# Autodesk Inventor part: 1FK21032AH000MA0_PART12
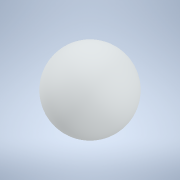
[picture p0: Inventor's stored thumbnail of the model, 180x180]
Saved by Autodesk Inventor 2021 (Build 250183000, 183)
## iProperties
Created: 2025-04
Part Number: 1FK21032AH000MA0_PART12
Material: Generic
Catalog Web Link: www.3dfindit.com
Description: -Servo synchronous motor
Document SubType Name: Modeling
Designer: psAdmin
Mass: 0.113097 g
Surface Area: 1.13097 cm^2
Volume: 0.113097 cm^3
Density: 1 g/cm^3
Appearance: PSOLRGB-212-217-219
Category: PARTsolutions
Title: 1FK21032AH000MA0_PART12
Author: Cadenas PARTsolutions
Comments: Servo synchronous motor
Sending System: PARTsolutions
Preprocessor: ST-DEVELOPER v19.3
PSOL_IDENT_0: {$CADENAS_DATA/23d-libs/siemens_ag/_cat_/45/10/1fk21032ah000ma0.prj},216 {VTYP=3D},{NB=1FK21032AH000
PSOL_IDENT_1: MA0_PART12},{LINA=1FK21032AH000MA0_PART12},{NN=1FK21032AH000MA0_PART12},{NOPRJ=TRUE},{DATE=19.08.202
PSOL_IDENT_2: 5 14:00:35},{GEOMDATE=30.07.2025 02:02:03},{VERSION=},{LINEID=10},{WBVAR=},{WBNUMERIC=}  {NB=1FK2103
PSOL_IDENT_3: 2AH000MA0_PART12},{LINA=1FK21032AH000MA0_PART12},{KT=DUMMY},{PREVIEW=../../../_pool_/14/8e/p_d211_xx
PSOL_IDENT_4: _00426j.png},{DESCSHORT=SIMOTICS S-1FK2 HD, SINAMICS S210 3AC 400V-480V, 0.59 Nm, 4500 rpm},{DESCLON
PSOL_IDENT_5: G=SIMOTICS S-1FK2 HD servo motor M0=0.64 Nm; PN = 0.28 kW at nN=4500 rpm (380-480 V); PN = 0.167 kW
PSOL_IDENT_6: at nN=2500 rpm (200-240 V); degree of protection IP64; cylindrical shaft D14 x 30 mm; absolute encod
PSOL_IDENT_7: er 22-bit + 12-bit multiturn (encoder AM22DQC); with OCC interface; plug size M17, rotatable; SIMOTI
PSOL_IDENT_8: CS S-1FK2 servomotorfor a wide range of uses in industrial environments. SIMOTICS S‑1FK2 servomotors
PSOL_IDENT_9: are compact synchronous motors with a high dynamic performance that set themselves apart as a resul
PSOL_IDENT_10: t of their high power density, degree of protection and overload capability. The motors are availabl
PSOL_IDENT_11: e in two variants: as High Dynamic variant (highest dynamic performance as a result of the low intri
PSOL_IDENT_12: nsic moment of inertia for applications demanding a high dynamic performance with low moved masses)
PSOL_IDENT_13: - and as Compact variant (precise and stable closed-loop control for medium up to large moved masses
PSOL_IDENT_14: as a result of a medium intrinsic moment of inertia). SIMOTICSS‑1FK2 servomotors fully exploit thei
PSOL_IDENT_15: r strengths in a system with the SINAMICSS210 frequency converter and simple connection using the on
PSOL_IDENT_16: e cable connection (OCC). Advantages include the short control and positioning times, fast and preci
PSOL_IDENT_17: se correction of disturbing quantities as well as stable control with a high dynamic performance. Th
PSOL_IDENT_18: e servo motors can be configured to address a wide range of requirements. For example with and witho
PSOL_IDENT_19: ut holding brake, IP64 or IP65 degree of protection, singleturn or multiturn absolute encoders - to
PSOL_IDENT_20: name just a few. Further, the servomotors are available in different shaft heights extending from 20
PSOL_IDENT_21: to 100. A shaft sealing ring is available to achieve an IP65 degree of protection and for subsequen
PSOL_IDENT_22: t mounting at the motor or as spare part. SIMOTICS - the optimum motor for each and every motion con
PSOL_IDENT_23: trol application.},{INTNO=195125335004},{SUPPLIERALTNO=1FK2103-2AH00-0MA0},{MANUID=1FK21032AH000MA0}
PSOL_IDENT_24: ,{MANUNAME=Siemens},{MANUTYPEDESC=SYNCHRONOUS MOTOR 1FK2 HD 0,64 NM},{AAU732=SIMOTICS},{AAO057=S-1FK
PSOL_IDENT_25: 2},{AAU734=SIMOTICS S-1FK2 HD servo motor M0=0.64 Nm; PN = 0.28 kW at nN=4500 rpm (380-480 V); PN =
PSOL_IDENT_26: 0.167 kW at nN=2500 rpm (200-240 V); degree of protection IP64; cylindrical shaft D14 x 30 mm; absol
PSOL_IDENT_27: ute encoder 22-bit + 12-bit multiturn (encoder AM22DQC); with OCC interface; plug size M17, rotatabl
PSOL_IDENT_28: e;},{AAW338=SYNCHRONOUS MOTOR 1FK2 HD 0,64 NM},{AAO742=SIMOTICS},{AAO663=4034106444624},{NOCUPEROU=1
PSOL_IDENT_29: },{PRICEQUANTITY=1},{QUANTITYMIN=1},{QUANTITYINT=1},{CTN=85015100},{COO=RO},{AAO676=1FK2103-2AH00-0M
PSOL_IDENT_30: A0},{AAO677=Siemens AG},{ORDERUNIT=C62},{CONTENTUNIT=C62}
NB: 1FK21032AH000MA0_PART12
NT: Servo synchronous motor
NBSYN: $MANUID._PART12
LINA: 1FK21032AH000MA0_PART12
CATALOG: SIEMENS
PREVIEW: ../../../_pool_/14/8e/p_d211_xx_00426j.png
DESCSHORT: SIMOTICS S-1FK2 HD, SINAMICS S210 3AC 400V-480V, 0.59 Nm, 4500 rpm
DESCLONG: SIMOTICS S-1FK2 HD servo motor M0=0.64 Nm; PN = 0.28 kW at nN=4500 rpm (380-480 V); PN = 0.167 kW at nN=2500 rpm (200-240 V); degree of protection IP64; cylindr
INTNO: 195125335004
SUPPLIERALTNO: 1FK2103-2AH00-0MA0
MANUID: 1FK21032AH000MA0
MANUNAME: Siemens
MANUTYPEDESC: SYNCHRONOUS MOTOR 1FK2 HD 0,64 NM
AAU732: SIMOTICS
AAO057: S-1FK2
AAU734: SIMOTICS S-1FK2 HD servo motor M0=0.64 Nm; PN = 0.28 kW at nN=4500 rpm (380-480 V); PN = 0.167 kW at nN=2500 rpm (200-240 V); degree of protection IP64; cylindr
AAW338: SYNCHRONOUS MOTOR 1FK2 HD 0,64 NM
AAO742: SIMOTICS
AAO663: 4034106444624.0
NOCUPEROU: 1
PRICEQUANTITY: 1
QUANTITYMIN: 1
QUANTITYINT: 1
CTN: 85015100
COO: RO
ARTICLENO: 1FK21032AH000MA0_PART12
BOMINFO: 1FK21032AH000MA0_PART12
CREATOR: CADENAS GmbH
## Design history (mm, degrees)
feature "2025_04_17_15_00_20_0760"
body "Solid1"
